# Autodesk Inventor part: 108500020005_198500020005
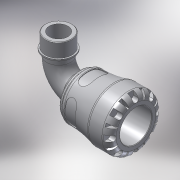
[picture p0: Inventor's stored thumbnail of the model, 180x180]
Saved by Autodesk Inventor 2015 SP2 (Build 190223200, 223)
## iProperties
Created: 2016-12
Part Number: 108500020005_198500020005
Material: PVC-Piping
Description: PLASSON 90° ELBOW WITH THREADED MALE OFFTAKE 20X1/2" SERIES 1
Document SubType Name: Modeling
Designer: KIM
Mass: 63.8623 g
Surface Area: 171.498 cm^2
Volume: 45.6159 cm^3
Density: 1.4 g/cm^3
Appearance: Smooth - White
Author: KIM
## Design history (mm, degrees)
derived "1085.ipt"
feature "Solid1::1085.ipt"
tag "TaggingFeature1"
body "Solid1"
other parameters: "d1" = 18.9, "d3" = 25, "d4" = 41, "d8" = 34.85, "d13" = 6.4, "d14" = 6.4, "d15" = 0, "d17" = 360 deg, "d19" = 8 deg, "d20" = 0.4, "d21" = 0.4, "d22" = 8 deg, "d24" = 0, "d26" = 360 deg, "d33" = 4.1, "d43" = 31.98, "d51" = 0.41, "d54" = 7, "d55" = 4.4, "d57" = 12.544, "d58" = 0, "d74" = 0, "d78" = 45, "d82" = 0.4, "d115" = 360 deg, "d207" = 90 deg, "d228" = 5.95, "d247" = 0.82, "d248" = 2.7, "d268" = 19.1675, "d269" = 2.7, "d270" = 66, "d276" = 20.955, "d277" = 16, "d278" = 23.0505, "d279" = 41, "d280" = 17.6, "d281" = 3.14325, "d283" = 18.8595, "d286" = 0, "d287" = 0, "d288" = 14.6685, "d290" = 6.56025, "d292" = 30 deg, "E_" = 41, "l_" = 45, "A_" = 66, "A_1" = 41, "l_2" = 16, "R_" = 20.955, "d9" = 8, "d11" = 41, "d12" = 25, "d289" = 14.6685
